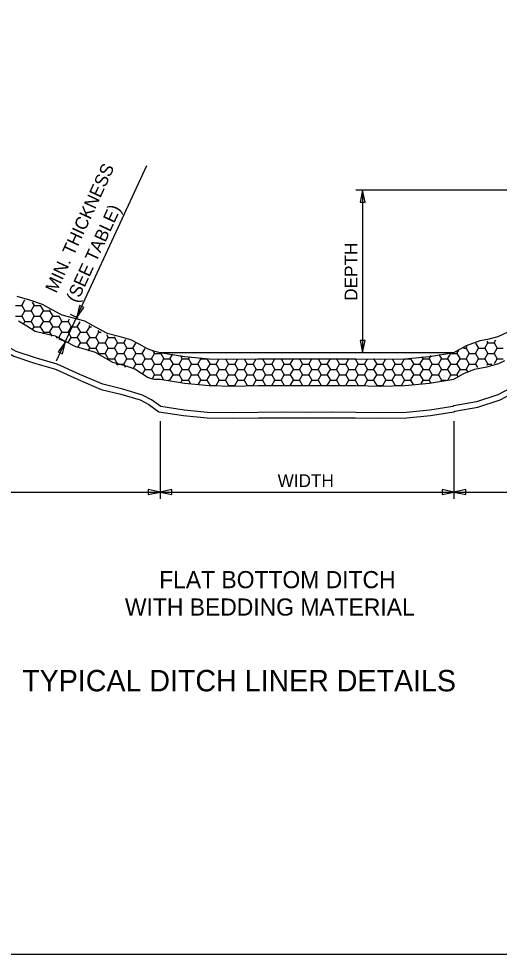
# Model space of a CAD drawing. Extents: x -439.1 to -407.9, y -458.1 to -436.2.
# Drawn here: x -431.29 to -425.67, y -458.05 to -447.12 of the extents above; entities that cross this region are included whole.
import ezdxf

# ---------------------------------------------------------------- set-up
doc = ezdxf.new("R2010")
doc.units = 0
doc.layers.add('Default', color=7, linetype='Continuous')
doc.layers.add('Draft_Named_Boundary', color=7, linetype='Continuous')

msp = doc.modelspace()

# ---------------------------------------------------------------- linework, layer by layer
at = {"layer": 'Default'}
for p, q in [((-430.849, -451.12), (-429.795, -448.839)), ((-421.625, -449.128), (-427.35, -449.128)), ((-427.271, -449.128), (-427.271, -451.022)), ((-431.328, -450.472), (-431.256, -450.472)), ((-431.256, -450.472), (-431.22, -450.409)), ((-431.256, -450.472), (-431.22, -450.534)), ((-431.22, -450.409), (-431.22, -450.409)), ((-431.22, -450.409), (-431.22, -450.409)), ((-431.148, -450.534), (-431.112, -450.472)), ((-431.133, -450.436), (-431.112, -450.472)), ((-431.112, -450.472), (-431.04, -450.472)), ((-431.04, -450.472), (-431.036, -450.466)), ((-431.04, -450.472), (-431.004, -450.534)), ((-431.328, -450.597), (-431.256, -450.597)), ((-431.256, -450.597), (-431.22, -450.534)), ((-431.256, -450.597), (-431.22, -450.659)), ((-431.22, -450.534), (-431.148, -450.534)), ((-431.148, -450.534), (-431.112, -450.597)), ((-431.148, -450.659), (-431.112, -450.597)), ((-431.112, -450.597), (-431.04, -450.597)), ((-431.04, -450.597), (-431.004, -450.534)), ((-431.04, -450.597), (-431.004, -450.659)), ((-431.004, -450.534), (-430.931, -450.534)), ((-430.931, -450.534), (-430.926, -450.526)), ((-430.931, -450.534), (-430.895, -450.597)), ((-430.931, -450.659), (-430.895, -450.597)), ((-430.895, -450.597), (-430.823, -450.597)), ((-430.823, -450.597), (-430.819, -450.589)), ((-430.823, -450.597), (-430.787, -450.659)), ((-430.597, -450.62), (-430.685, -450.579)), ((-431.238, -450.69), (-431.22, -450.659)), ((-431.22, -450.659), (-431.148, -450.659)), ((-431.148, -450.659), (-431.112, -450.722)), ((-431.131, -450.755), (-431.112, -450.722)), ((-431.112, -450.722), (-431.04, -450.722)), ((-431.04, -450.722), (-431.004, -450.659)), ((-431.04, -450.722), (-431.004, -450.784)), ((-431.004, -450.659), (-430.931, -450.659)), ((-430.931, -450.659), (-430.895, -450.722)), ((-430.931, -450.784), (-430.895, -450.722)), ((-430.895, -450.722), (-430.823, -450.722)), ((-430.823, -450.722), (-430.787, -450.659)), ((-430.823, -450.722), (-430.787, -450.784)), ((-430.787, -450.659), (-430.715, -450.659)), ((-430.715, -450.659), (-430.699, -450.631)), ((-430.715, -450.659), (-430.679, -450.722)), ((-430.715, -450.784), (-430.679, -450.722)), ((-430.679, -450.722), (-430.607, -450.722)), ((-430.607, -450.722), (-430.572, -450.663)), ((-430.607, -450.722), (-430.571, -450.784)), ((-430.498, -450.784), (-430.462, -450.722)), ((-430.471, -450.707), (-430.462, -450.722)), ((-430.462, -450.722), (-430.443, -450.722)), ((-431.012, -450.799), (-431.004, -450.784)), ((-431.004, -450.784), (-430.931, -450.784)), ((-430.931, -450.784), (-430.904, -450.832)), ((-430.823, -450.847), (-430.787, -450.784)), ((-430.787, -450.784), (-430.715, -450.784)), ((-430.715, -450.784), (-430.679, -450.847)), ((-430.607, -450.847), (-430.571, -450.784)), ((-430.571, -450.784), (-430.498, -450.784)), ((-430.498, -450.784), (-430.462, -450.847)), ((-430.39, -450.847), (-430.354, -450.784)), ((-430.366, -450.765), (-430.354, -450.784)), ((-430.354, -450.784), (-430.329, -450.784)), ((-430.266, -450.812), (-430.246, -450.847)), ((-430.174, -450.847), (-430.167, -450.836)), ((-430.854, -450.847), (-430.823, -450.847)), ((-430.823, -450.847), (-430.817, -450.858)), ((-430.73, -450.907), (-430.818, -450.866)), ((-430.712, -450.905), (-430.679, -450.847)), ((-430.679, -450.847), (-430.607, -450.847)), ((-430.607, -450.847), (-430.571, -450.909)), ((-430.598, -450.957), (-430.571, -450.909)), ((-430.571, -450.909), (-430.498, -450.909)), ((-430.498, -450.909), (-430.462, -450.847)), ((-430.498, -450.909), (-430.462, -450.972)), ((-430.462, -450.847), (-430.39, -450.847)), ((-430.39, -450.847), (-430.354, -450.909)), ((-430.39, -450.972), (-430.354, -450.909)), ((-430.354, -450.909), (-430.282, -450.909)), ((-430.282, -450.909), (-430.246, -450.847)), ((-430.282, -450.909), (-430.246, -450.972)), ((-430.246, -450.847), (-430.174, -450.847)), ((-430.174, -450.847), (-430.138, -450.909)), ((-430.174, -450.972), (-430.138, -450.909)), ((-430.138, -450.909), (-430.065, -450.909)), ((-430.065, -450.909), (-430.041, -450.866)), ((-430.065, -450.909), (-430.029, -450.972)), ((-429.957, -450.972), (-429.924, -450.915)), ((-425.951, -450.912), (-425.916, -450.972)), ((-425.844, -450.972), (-425.808, -450.909)), ((-425.819, -450.89), (-425.808, -450.909)), ((-425.808, -450.909), (-425.735, -450.909)), ((-425.735, -450.909), (-425.714, -450.873)), ((-425.735, -450.909), (-425.699, -450.972)), ((-430.48, -451.002), (-430.462, -450.972)), ((-430.462, -450.972), (-430.39, -450.972)), ((-430.39, -450.972), (-430.354, -451.034)), ((-430.361, -451.047), (-430.354, -451.034)), ((-430.354, -451.034), (-430.282, -451.034)), ((-430.282, -451.034), (-430.246, -450.972)), ((-430.282, -451.034), (-430.246, -451.097)), ((-430.246, -450.972), (-430.174, -450.972)), ((-430.174, -450.972), (-430.138, -451.034)), ((-430.174, -451.097), (-430.138, -451.034)), ((-430.138, -451.034), (-430.065, -451.034)), ((-430.065, -451.034), (-430.029, -450.972)), ((-430.065, -451.034), (-430.029, -451.097)), ((-430.029, -450.972), (-429.957, -450.972)), ((-429.957, -450.972), (-429.921, -451.034)), ((-429.957, -451.097), (-429.921, -451.034)), ((-429.921, -451.034), (-429.849, -451.034)), ((-429.849, -451.034), (-429.815, -450.976)), ((-429.849, -451.034), (-429.813, -451.097)), ((-429.741, -451.097), (-429.705, -451.034)), ((-429.723, -451.002), (-429.705, -451.034)), ((-429.705, -451.034), (-429.64, -451.034)), ((-429.64, -451.022), (-426.202, -451.022)), ((-429.64, -451.034), (-429.632, -451.034)), ((-429.632, -451.034), (-429.626, -451.024)), ((-429.632, -451.034), (-429.596, -451.097)), ((-429.524, -451.097), (-429.492, -451.041)), ((-429.405, -451.053), (-429.38, -451.097)), ((-426.493, -451.097), (-426.47, -451.057)), ((-426.379, -451.045), (-426.349, -451.097)), ((-426.277, -451.097), (-426.241, -451.034)), ((-426.245, -451.027), (-426.241, -451.034)), ((-426.241, -451.034), (-426.203, -451.034)), ((-426.203, -451.034), (-426.168, -451.034)), ((-426.168, -451.034), (-426.146, -450.997)), ((-426.168, -451.034), (-426.132, -451.097)), ((-426.092, -450.972), (-426.06, -450.972)), ((-426.06, -450.972), (-426.049, -450.953)), ((-426.06, -450.972), (-426.024, -451.034)), ((-426.06, -451.097), (-426.024, -451.034)), ((-426.024, -451.034), (-425.952, -451.034)), ((-425.952, -451.034), (-425.916, -450.972)), ((-425.952, -451.034), (-425.916, -451.097)), ((-425.916, -450.972), (-425.844, -450.972)), ((-425.844, -450.972), (-425.808, -451.034)), ((-425.844, -451.097), (-425.808, -451.034)), ((-425.808, -451.034), (-425.735, -451.034)), ((-425.735, -451.034), (-425.699, -450.972)), ((-425.735, -451.034), (-425.699, -451.097)), ((-425.699, -450.972), (-425.627, -450.972)), ((-430.252, -451.107), (-430.246, -451.097)), ((-430.246, -451.097), (-430.174, -451.097)), ((-430.174, -451.097), (-430.138, -451.159)), ((-430.144, -451.17), (-430.138, -451.159)), ((-430.138, -451.159), (-430.065, -451.159)), ((-430.065, -451.159), (-430.029, -451.097)), ((-430.065, -451.159), (-430.046, -451.193)), ((-430.029, -451.097), (-429.957, -451.097)), ((-429.957, -451.097), (-429.921, -451.159)), ((-429.953, -451.215), (-429.921, -451.159)), ((-429.921, -451.159), (-429.849, -451.159)), ((-429.849, -451.159), (-429.813, -451.097)), ((-429.849, -451.159), (-429.813, -451.222)), ((-429.813, -451.097), (-429.741, -451.097)), ((-429.741, -451.097), (-429.705, -451.159)), ((-429.741, -451.222), (-429.705, -451.159)), ((-429.705, -451.159), (-429.64, -451.159)), ((-429.64, -451.159), (-429.632, -451.159)), ((-429.632, -451.159), (-429.596, -451.097)), ((-429.632, -451.159), (-429.596, -451.222)), ((-429.596, -451.097), (-429.524, -451.097)), ((-429.524, -451.097), (-429.488, -451.159)), ((-429.524, -451.222), (-429.488, -451.159)), ((-429.488, -451.159), (-429.416, -451.159)), ((-429.416, -451.159), (-429.38, -451.097)), ((-429.416, -451.159), (-429.38, -451.222)), ((-429.38, -451.097), (-429.308, -451.097)), ((-429.308, -451.097), (-429.291, -451.068)), ((-429.308, -451.097), (-429.272, -451.159)), ((-429.308, -451.222), (-429.272, -451.159)), ((-429.272, -451.159), (-429.199, -451.159)), ((-429.199, -451.159), (-429.163, -451.097)), ((-429.199, -451.159), (-429.163, -451.222)), ((-429.171, -451.083), (-429.163, -451.097)), ((-429.163, -451.097), (-429.091, -451.097)), ((-429.091, -451.097), (-429.09, -451.094)), ((-429.091, -451.097), (-429.055, -451.159)), ((-429.091, -451.222), (-429.055, -451.159)), ((-429.055, -451.159), (-428.983, -451.159)), ((-428.983, -451.159), (-428.947, -451.097)), ((-428.983, -451.159), (-428.947, -451.222)), ((-428.875, -451.097), (-428.839, -451.159)), ((-428.875, -451.222), (-428.839, -451.159)), ((-428.839, -451.159), (-428.766, -451.159)), ((-428.766, -451.159), (-428.73, -451.097)), ((-428.766, -451.159), (-428.73, -451.222)), ((-428.658, -451.097), (-428.622, -451.159)), ((-428.658, -451.222), (-428.622, -451.159)), ((-428.622, -451.159), (-428.55, -451.159)), ((-428.55, -451.159), (-428.514, -451.097)), ((-428.55, -451.159), (-428.514, -451.222)), ((-428.442, -451.097), (-428.406, -451.159)), ((-428.442, -451.222), (-428.406, -451.159)), ((-428.406, -451.159), (-428.333, -451.159)), ((-428.333, -451.159), (-428.297, -451.097)), ((-428.333, -451.159), (-428.297, -451.222)), ((-428.225, -451.097), (-428.189, -451.159)), ((-428.225, -451.222), (-428.189, -451.159)), ((-428.189, -451.159), (-428.117, -451.159)), ((-428.117, -451.159), (-428.081, -451.097)), ((-428.117, -451.159), (-428.081, -451.222)), ((-428.009, -451.097), (-427.973, -451.159)), ((-428.009, -451.222), (-427.973, -451.159)), ((-427.973, -451.159), (-427.9, -451.159)), ((-427.9, -451.159), (-427.864, -451.097)), ((-427.9, -451.159), (-427.864, -451.222)), ((-427.792, -451.097), (-427.756, -451.159)), ((-427.792, -451.222), (-427.756, -451.159)), ((-427.756, -451.159), (-427.684, -451.159)), ((-427.684, -451.159), (-427.648, -451.097)), ((-427.684, -451.159), (-427.648, -451.222)), ((-427.576, -451.097), (-427.54, -451.159)), ((-427.576, -451.222), (-427.54, -451.159)), ((-427.54, -451.159), (-427.467, -451.159)), ((-427.467, -451.159), (-427.431, -451.097)), ((-427.467, -451.159), (-427.431, -451.222)), ((-427.359, -451.097), (-427.323, -451.159)), ((-427.359, -451.222), (-427.323, -451.159)), ((-427.323, -451.159), (-427.251, -451.159)), ((-427.251, -451.159), (-427.215, -451.097)), ((-427.251, -451.159), (-427.215, -451.222)), ((-427.143, -451.097), (-427.107, -451.159)), ((-427.143, -451.222), (-427.107, -451.159)), ((-427.107, -451.159), (-427.034, -451.159)), ((-427.034, -451.159), (-426.998, -451.097)), ((-427.034, -451.159), (-426.998, -451.222)), ((-426.926, -451.097), (-426.89, -451.159)), ((-426.926, -451.222), (-426.89, -451.159)), ((-426.89, -451.159), (-426.818, -451.159)), ((-426.818, -451.159), (-426.782, -451.097)), ((-426.818, -451.159), (-426.782, -451.222)), ((-426.776, -451.097), (-426.71, -451.097)), ((-426.71, -451.097), (-426.704, -451.088)), ((-426.71, -451.097), (-426.674, -451.159)), ((-426.71, -451.222), (-426.674, -451.159)), ((-426.674, -451.159), (-426.601, -451.159)), ((-426.601, -451.159), (-426.565, -451.097)), ((-426.601, -451.159), (-426.565, -451.222)), ((-426.58, -451.071), (-426.565, -451.097)), ((-426.565, -451.097), (-426.493, -451.097)), ((-426.493, -451.097), (-426.457, -451.159)), ((-426.493, -451.222), (-426.457, -451.159)), ((-426.457, -451.159), (-426.385, -451.159)), ((-426.385, -451.159), (-426.349, -451.097)), ((-426.385, -451.159), (-426.349, -451.222)), ((-426.349, -451.097), (-426.277, -451.097)), ((-426.277, -451.097), (-426.241, -451.159)), ((-426.277, -451.222), (-426.241, -451.159)), ((-426.241, -451.159), (-426.203, -451.159)), ((-426.203, -451.159), (-426.168, -451.159)), ((-426.168, -451.159), (-426.132, -451.097)), ((-426.168, -451.159), (-426.132, -451.222)), ((-426.132, -451.097), (-426.06, -451.097)), ((-426.06, -451.097), (-426.024, -451.159)), ((-426.06, -451.222), (-426.024, -451.159)), ((-426.024, -451.159), (-425.952, -451.159)), ((-425.952, -451.159), (-425.916, -451.097)), ((-425.952, -451.159), (-425.929, -451.199)), ((-425.916, -451.097), (-425.844, -451.097)), ((-425.844, -451.097), (-425.808, -451.159)), ((-425.815, -451.172), (-425.808, -451.159)), ((-425.808, -451.159), (-425.762, -451.159)), ((-425.731, -451.152), (-425.699, -451.097)), ((-425.699, -451.097), (-425.627, -451.097)), ((-429.845, -451.277), (-429.813, -451.222)), ((-429.813, -451.222), (-429.741, -451.222)), ((-429.741, -451.222), (-429.705, -451.284)), ((-429.632, -451.284), (-429.596, -451.222)), ((-429.596, -451.222), (-429.524, -451.222)), ((-429.524, -451.222), (-429.488, -451.284)), ((-429.416, -451.284), (-429.38, -451.222)), ((-429.38, -451.222), (-429.308, -451.222)), ((-429.308, -451.222), (-429.272, -451.284)), ((-429.199, -451.284), (-429.163, -451.222)), ((-429.163, -451.222), (-429.091, -451.222)), ((-429.091, -451.222), (-429.055, -451.284)), ((-428.983, -451.284), (-428.947, -451.222)), ((-428.947, -451.222), (-428.875, -451.222)), ((-428.875, -451.222), (-428.839, -451.284)), ((-428.766, -451.284), (-428.73, -451.222)), ((-428.73, -451.222), (-428.658, -451.222)), ((-428.658, -451.222), (-428.622, -451.284)), ((-428.55, -451.284), (-428.514, -451.222)), ((-428.514, -451.222), (-428.442, -451.222)), ((-428.442, -451.222), (-428.406, -451.284)), ((-428.333, -451.284), (-428.297, -451.222)), ((-428.297, -451.222), (-428.225, -451.222)), ((-428.225, -451.222), (-428.189, -451.284)), ((-428.117, -451.284), (-428.081, -451.222)), ((-428.081, -451.222), (-428.009, -451.222)), ((-428.009, -451.222), (-427.973, -451.284)), ((-427.9, -451.284), (-427.864, -451.222)), ((-427.864, -451.222), (-427.792, -451.222)), ((-427.792, -451.222), (-427.756, -451.284)), ((-427.684, -451.284), (-427.648, -451.222)), ((-427.648, -451.222), (-427.576, -451.222)), ((-427.576, -451.222), (-427.54, -451.284)), ((-427.467, -451.284), (-427.431, -451.222)), ((-427.431, -451.222), (-427.359, -451.222)), ((-427.359, -451.222), (-427.323, -451.284)), ((-427.251, -451.284), (-427.215, -451.222)), ((-427.215, -451.222), (-427.143, -451.222)), ((-427.143, -451.222), (-427.107, -451.284)), ((-427.034, -451.284), (-426.998, -451.222)), ((-426.998, -451.222), (-426.926, -451.222)), ((-426.926, -451.222), (-426.89, -451.284)), ((-426.818, -451.284), (-426.782, -451.222)), ((-426.782, -451.222), (-426.71, -451.222)), ((-426.71, -451.222), (-426.674, -451.284)), ((-426.601, -451.284), (-426.565, -451.222)), ((-426.565, -451.222), (-426.493, -451.222)), ((-426.493, -451.222), (-426.457, -451.284)), ((-426.385, -451.284), (-426.349, -451.222)), ((-426.349, -451.222), (-426.277, -451.222)), ((-426.277, -451.222), (-426.241, -451.284)), ((-426.168, -451.284), (-426.132, -451.222)), ((-426.132, -451.222), (-426.06, -451.222)), ((-426.06, -451.222), (-426.042, -451.253)), ((-429.729, -451.327), (-429.705, -451.284)), ((-429.705, -451.284), (-429.64, -451.284)), ((-429.64, -451.284), (-429.632, -451.284)), ((-429.632, -451.284), (-429.601, -451.34)), ((-429.545, -451.347), (-429.524, -451.347)), ((-429.524, -451.347), (-429.488, -451.284)), ((-429.524, -451.347), (-429.522, -451.35)), ((-429.488, -451.284), (-429.416, -451.284)), ((-429.416, -451.284), (-429.38, -451.347)), ((-429.391, -451.367), (-429.38, -451.347)), ((-429.38, -451.347), (-429.308, -451.347)), ((-429.308, -451.347), (-429.272, -451.284)), ((-429.308, -451.347), (-429.288, -451.381)), ((-429.272, -451.284), (-429.199, -451.284)), ((-429.199, -451.284), (-429.163, -451.347)), ((-429.19, -451.393), (-429.163, -451.347)), ((-429.163, -451.347), (-429.091, -451.347)), ((-429.091, -451.347), (-429.055, -451.284)), ((-429.091, -451.347), (-429.055, -451.409)), ((-429.055, -451.284), (-428.983, -451.284)), ((-428.983, -451.284), (-428.947, -451.347)), ((-428.983, -451.409), (-428.947, -451.347)), ((-428.947, -451.347), (-428.875, -451.347)), ((-428.875, -451.347), (-428.839, -451.284)), ((-428.875, -451.347), (-428.839, -451.409)), ((-428.839, -451.284), (-428.766, -451.284)), ((-428.766, -451.284), (-428.73, -451.347)), ((-428.766, -451.409), (-428.73, -451.347)), ((-428.73, -451.347), (-428.658, -451.347)), ((-428.658, -451.347), (-428.622, -451.284)), ((-428.658, -451.347), (-428.622, -451.409)), ((-428.622, -451.284), (-428.55, -451.284)), ((-428.55, -451.284), (-428.514, -451.347)), ((-428.55, -451.409), (-428.514, -451.347)), ((-428.514, -451.347), (-428.442, -451.347)), ((-428.442, -451.347), (-428.406, -451.284)), ((-428.442, -451.347), (-428.406, -451.409)), ((-428.406, -451.284), (-428.333, -451.284)), ((-428.333, -451.284), (-428.297, -451.347)), ((-428.333, -451.409), (-428.297, -451.347)), ((-428.297, -451.347), (-428.225, -451.347)), ((-428.225, -451.347), (-428.189, -451.284)), ((-428.225, -451.347), (-428.189, -451.409)), ((-428.189, -451.284), (-428.117, -451.284)), ((-428.117, -451.284), (-428.081, -451.347)), ((-428.117, -451.409), (-428.081, -451.347)), ((-428.081, -451.347), (-428.009, -451.347)), ((-428.009, -451.347), (-427.973, -451.284)), ((-428.009, -451.347), (-427.973, -451.409)), ((-427.973, -451.284), (-427.9, -451.284)), ((-427.9, -451.284), (-427.864, -451.347)), ((-427.9, -451.409), (-427.864, -451.347)), ((-427.864, -451.347), (-427.792, -451.347)), ((-427.792, -451.347), (-427.756, -451.284)), ((-427.792, -451.347), (-427.756, -451.409)), ((-427.756, -451.284), (-427.684, -451.284)), ((-427.684, -451.284), (-427.648, -451.347)), ((-427.684, -451.409), (-427.648, -451.347)), ((-427.648, -451.347), (-427.576, -451.347)), ((-427.576, -451.347), (-427.54, -451.284)), ((-427.576, -451.347), (-427.54, -451.409)), ((-427.54, -451.284), (-427.467, -451.284)), ((-427.467, -451.284), (-427.431, -451.347)), ((-427.467, -451.409), (-427.431, -451.347)), ((-427.431, -451.347), (-427.359, -451.347)), ((-427.359, -451.347), (-427.323, -451.284)), ((-427.359, -451.347), (-427.323, -451.409)), ((-427.323, -451.284), (-427.251, -451.284)), ((-427.251, -451.284), (-427.215, -451.347)), ((-427.251, -451.409), (-427.215, -451.347)), ((-427.215, -451.347), (-427.143, -451.347)), ((-427.143, -451.347), (-427.107, -451.284)), ((-427.143, -451.347), (-427.107, -451.409)), ((-427.107, -451.284), (-427.034, -451.284)), ((-427.034, -451.284), (-426.998, -451.347)), ((-427.034, -451.409), (-426.998, -451.347)), ((-426.998, -451.347), (-426.926, -451.347)), ((-426.926, -451.347), (-426.89, -451.284)), ((-426.926, -451.347), (-426.89, -451.409)), ((-426.89, -451.284), (-426.818, -451.284)), ((-426.818, -451.284), (-426.782, -451.347)), ((-426.818, -451.409), (-426.782, -451.347)), ((-426.782, -451.347), (-426.71, -451.347)), ((-426.71, -451.347), (-426.674, -451.284)), ((-426.71, -451.347), (-426.681, -451.397)), ((-426.674, -451.284), (-426.601, -451.284)), ((-426.601, -451.284), (-426.565, -451.347)), ((-426.587, -451.385), (-426.565, -451.347)), ((-426.565, -451.347), (-426.493, -451.347)), ((-426.493, -451.347), (-426.457, -451.284)), ((-426.493, -451.347), (-426.479, -451.371)), ((-426.457, -451.284), (-426.385, -451.284)), ((-426.385, -451.284), (-426.349, -451.347)), ((-426.353, -451.354), (-426.349, -451.347)), ((-426.349, -451.347), (-426.298, -451.347)), ((-426.275, -451.344), (-426.241, -451.284)), ((-426.241, -451.284), (-426.203, -451.284)), ((-426.203, -451.284), (-426.168, -451.284)), ((-426.168, -451.284), (-426.154, -451.31)), ((-429.055, -451.409), (-428.983, -451.409)), ((-429.055, -451.409), (-429.055, -451.409)), ((-428.983, -451.409), (-428.983, -451.409)), ((-428.839, -451.409), (-428.766, -451.409)), ((-428.839, -451.409), (-428.839, -451.409)), ((-428.766, -451.409), (-428.766, -451.409)), ((-428.622, -451.409), (-428.55, -451.409)), ((-428.622, -451.409), (-428.622, -451.409)), ((-428.55, -451.409), (-428.55, -451.409)), ((-428.406, -451.409), (-428.333, -451.409)), ((-428.406, -451.409), (-428.406, -451.409)), ((-428.333, -451.409), (-428.333, -451.409)), ((-428.189, -451.409), (-428.117, -451.409)), ((-428.189, -451.409), (-428.189, -451.409)), ((-428.117, -451.409), (-428.117, -451.409)), ((-427.973, -451.409), (-427.9, -451.409)), ((-427.973, -451.409), (-427.973, -451.409)), ((-427.9, -451.409), (-427.9, -451.409)), ((-427.756, -451.409), (-427.684, -451.409)), ((-427.756, -451.409), (-427.756, -451.409)), ((-427.684, -451.409), (-427.684, -451.409)), ((-427.54, -451.409), (-427.467, -451.409)), ((-427.54, -451.409), (-427.54, -451.409)), ((-427.467, -451.409), (-427.467, -451.409)), ((-427.323, -451.409), (-427.251, -451.409)), ((-427.323, -451.409), (-427.323, -451.409)), ((-427.251, -451.409), (-427.251, -451.409)), ((-427.107, -451.409), (-427.034, -451.409)), ((-427.107, -451.409), (-427.107, -451.409)), ((-427.034, -451.409), (-427.034, -451.409)), ((-426.89, -451.409), (-426.818, -451.409)), ((-426.89, -451.409), (-426.89, -451.409)), ((-426.818, -451.409), (-426.818, -451.409)), ((-426.203, -451.647), (-426.216, -451.655)), ((-426.204, -451.716), (-426.195, -451.709)), ((-429.64, -451.826), (-429.64, -452.73)), ((-426.203, -451.826), (-426.203, -452.73)), ((-435.013, -452.652), (-429.64, -452.652)), ((-429.64, -452.652), (-426.203, -452.652)), ((-426.203, -452.652), (-421.515, -452.652))]:
    msp.add_line(p, q, dxfattribs=at)
for points in [[(-427.243, -449.266), (-427.271, -449.128), (-427.3, -449.266)], [(-430.582, -450.474), (-430.614, -450.612), (-430.53, -450.498)], [(-430.582, -450.474), (-430.614, -450.612), (-430.53, -450.498)], [(-430.779, -451.037), (-430.747, -450.899), (-430.831, -451.013)], [(-430.779, -451.037), (-430.747, -450.899), (-430.831, -451.013)], [(-427.3, -450.884), (-427.271, -451.022), (-427.243, -450.884)], [(-429.779, -452.681), (-429.64, -452.652), (-429.779, -452.623)], [(-429.502, -452.623), (-429.64, -452.652), (-429.502, -452.681)], [(-426.341, -452.681), (-426.203, -452.652), (-426.341, -452.623)], [(-426.065, -452.623), (-426.203, -452.652), (-426.065, -452.681)]]:
    msp.add_lwpolyline(points, close=True, dxfattribs=at)
for points in [[(-421.515, -449.753), (-421.792, -449.887), (-422.072, -450.015), (-422.476, -450.193), (-422.682, -450.27), (-422.895, -450.33), (-423.195, -450.389), (-423.343, -450.422), (-423.486, -450.467), (-423.69, -450.568), (-423.884, -450.694), (-424.077, -450.825), (-424.277, -450.94), (-424.496, -451.027), (-424.724, -451.095), (-424.952, -451.161), (-425.173, -451.244), (-425.43, -451.382), (-425.689, -451.518), (-425.941, -451.599), (-426.203, -451.647)], [(-426.195, -451.709), (-425.924, -451.66), (-425.664, -451.575), (-425.405, -451.44), (-425.147, -451.301), (-424.926, -451.218), (-424.698, -451.151), (-424.47, -451.084), (-424.25, -450.997), (-424.051, -450.882), (-423.859, -450.752), (-423.666, -450.626), (-423.463, -450.526), (-423.322, -450.481), (-423.176, -450.449), (-422.881, -450.391), (-422.665, -450.33), (-422.456, -450.252), (-422.046, -450.071), (-421.765, -449.943), (-421.443, -449.787)], [(-429.63, -451.655), (-429.74, -451.577), (-429.846, -451.519), (-430.076, -451.45), (-430.31, -451.393), (-430.576, -451.278), (-430.841, -451.158), (-431.084, -451.09), (-431.322, -451.01), (-431.457, -450.932), (-431.585, -450.841), (-431.714, -450.751), (-431.85, -450.676), (-431.999, -450.628), (-432.155, -450.594), (-432.45, -450.52), (-432.589, -450.462), (-432.718, -450.38), (-432.818, -450.297), (-432.87, -450.264), (-432.926, -450.243), (-433.002, -450.241), (-433.078, -450.259)], [(-433.067, -450.321), (-432.998, -450.304), (-432.939, -450.304), (-432.89, -450.323), (-432.845, -450.354), (-432.757, -450.429), (-432.622, -450.515), (-432.477, -450.577), (-432.167, -450.656), (-432.018, -450.688), (-431.875, -450.734), (-431.739, -450.808), (-431.611, -450.898), (-431.483, -450.989), (-431.349, -451.067), (-431.108, -451.147), (-430.862, -451.217), (-430.596, -451.337), (-430.329, -451.453), (-430.098, -451.508), (-429.872, -451.576), (-429.772, -451.631), (-429.654, -451.714)], [(-431.313, -450.366), (-431.165, -450.409), (-431.019, -450.456), (-430.904, -450.521), (-430.788, -450.582), (-430.656, -450.619), (-430.524, -450.654), (-430.39, -450.726), (-430.256, -450.797), (-430.121, -450.832), (-429.987, -450.87), (-429.889, -450.923), (-429.792, -450.977), (-429.717, -451.004), (-429.64, -451.022)], [(-431.293, -450.651), (-431.197, -450.712), (-431.1, -450.772), (-430.985, -450.801), (-430.867, -450.827), (-430.748, -450.889), (-430.63, -450.953), (-430.515, -450.985), (-430.4, -451.019), (-430.298, -451.078), (-430.196, -451.137), (-430.065, -451.172), (-429.936, -451.212), (-429.858, -451.265), (-429.778, -451.315), (-429.711, -451.332), (-429.64, -451.334)], [(-426.203, -451.022), (-426.056, -450.94), (-425.898, -450.882), (-425.792, -450.861), (-425.688, -450.837), (-425.511, -450.752)], [(-429.64, -451.022), (-429.355, -451.07), (-429.067, -451.097), (-428.781, -451.102), (-428.495, -451.097), (-428.208, -451.096), (-427.922, -451.097), (-427.635, -451.096), (-427.349, -451.097), (-427.062, -451.102), (-426.776, -451.097), (-426.488, -451.07), (-426.203, -451.022)], [(-426.203, -451.334), (-426.087, -451.267), (-425.963, -451.217), (-425.818, -451.188), (-425.677, -451.151), (-425.61, -451.115)], [(-429.64, -451.334), (-429.355, -451.382), (-429.067, -451.409), (-428.781, -451.414), (-428.495, -451.409), (-428.208, -451.409), (-427.922, -451.409), (-427.635, -451.409), (-427.349, -451.409), (-427.062, -451.414), (-426.776, -451.409), (-426.488, -451.382), (-426.203, -451.334)], [(-429.654, -451.714), (-429.366, -451.759), (-429.087, -451.784), (-428.789, -451.789), (-428.49, -451.784), (-428.206, -451.784), (-427.922, -451.784), (-427.638, -451.784), (-427.354, -451.784), (-427.055, -451.789), (-426.756, -451.784), (-426.479, -451.759), (-426.204, -451.716)], [(-426.216, -451.655), (-426.487, -451.697), (-426.76, -451.722), (-427.056, -451.727), (-427.353, -451.722), (-427.637, -451.721), (-427.922, -451.722), (-428.206, -451.721), (-428.491, -451.722), (-428.787, -451.727), (-429.084, -451.722), (-429.359, -451.697), (-429.63, -451.655)]]:
    msp.add_lwpolyline(points, dxfattribs=at)
at = {"layer": 'Draft_Named_Boundary'}
msp.add_lwpolyline([(-439.109, -458.051), (-407.859, -458.051), (-407.859, -437.676), (-439.109, -437.676)], close=True, dxfattribs=at)

# ---------------------------------------------------------------- texts
at = {"layer": 'Default'}
for s, rotation, p in [('MIN. THICKNESS ', 65.2, (-430.853, -450.338)), ('(SEE TABLE)', 65.2, (-430.607, -450.452)), ('DEPTH', 90, (-427.332, -450.419))]:
    msp.add_text(s, height=0.15, rotation=rotation, dxfattribs=at).set_placement(p)
for s, height, p in [('WIDTH', 0.15, (-428.265, -452.594)), ('FLAT BOTTOM DITCH', 0.2, (-429.65, -453.775)), ('WITH BEDDING MATERIAL', 0.2, (-430.05, -454.095)), ('TYPICAL DITCH LINER DETAILS', 0.25, (-431.251, -454.98))]:
    msp.add_text(s, height=height, dxfattribs=at).set_placement(p)

doc.saveas('drawing.dxf')
